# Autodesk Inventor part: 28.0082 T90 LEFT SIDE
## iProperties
Created: 2007-04
Part Number: 28.0082 T90 LEFT SIDE
Document SubType Name: Modeling
Designer: Andy Moles
Material: Aluminum-6061
Mass: 895.865 g
Surface Area: 541.018 cm^2
Volume: 330.577 cm^3
Density: 2.71 g/cm^3
Author: Andy Moles
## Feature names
1. Extrusion1
2. Chamfer1
3. Hole1
4. Hole2
5. Hole3
6. Hole4
7. Hole5
8. Extrusion2
9. Extrusion3
10. Hole6
11. Extrusion4
12. Mirror1
13. Hole7
14. Hole8
15. Hole9
16. Hole10
